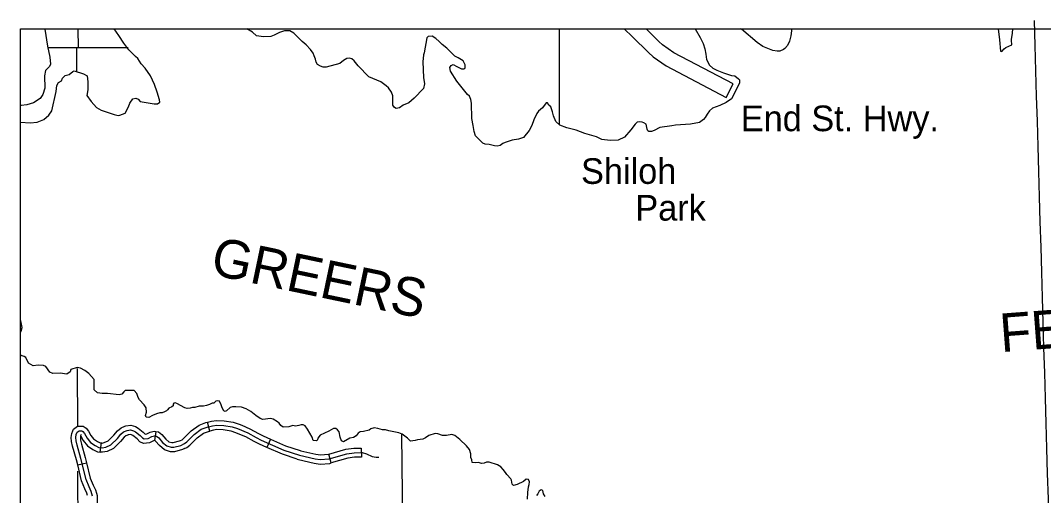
# Model space of a CAD drawing. Extents: x 1212896 to 1368412, y 378476 to 478763.
# Drawn here: x 1257400 to 1274256, y 429817 to 437641 of the extents above; entities that cross this region are included whole.
import ezdxf

# ---------------------------------------------------------------- set-up
doc = ezdxf.new("R2010")
doc.units = 0
for name, color, linetype in [('1', 7, 'Continuous'), ('Level 10', 7, 'Continuous'), ('Level 31', 7, 'Continuous'), ('Level 4', 7, 'Continuous'), ('Level 41', 7, 'Continuous'), ('Level 5', 7, 'Continuous'), ('Level 6', 7, 'Continuous'), ('Level 60', 7, 'Continuous'), ('Level 7', 7, 'Continuous'), ('Level 9', 7, 'Continuous')]:
    doc.layers.add(name, color=color, linetype=linetype)

msp = doc.modelspace()

# ---------------------------------------------------------------- linework, layer by layer
at = {"layer": '1'}
msp.add_lwpolyline([(1257400, 437504), (1319317, 437504), (1319317, 388319), (1257400, 388319)], close=True, dxfattribs=at)
at = {"layer": 'Level 10'}
msp.add_line((1269029, 436374), (1269145, 436596), dxfattribs=at)
for points in [[(1267347, 437504), (1267485, 437373), (1267745, 437111), (1267825, 437042), (1268037, 436896), (1269029, 436374)], [(1269145, 436596), (1268166, 437110), (1267978, 437240), (1267915, 437294), (1267707, 437504)]]:
    msp.add_lwpolyline(points, dxfattribs=at)
at = {"layer": 'Level 31'}
for p, q in [((1260518, 430879), (1260481, 431025)), ((1259629, 430873), (1259606, 430725)), ((1260987, 430836), (1260987, 430836)), ((1258716, 430534), (1258735, 430683)), ((1259178, 430819), (1259178, 430819)), ((1259606, 430725), (1259611, 430724)), ((1261521, 430745), (1261461, 430607)), ((1261461, 430607), (1261461, 430607)), ((1262522, 430354), (1262480, 430498)), ((1263016, 430600), (1263017, 430450)), ((1258343, 430321), (1258489, 430357))]:
    msp.add_line(p, q, dxfattribs=at)
for points in [[(1260038, 430725), (1260062, 430737), (1260091, 430760), (1260213, 430881), (1260342, 430978), (1260454, 431018), (1260481, 431025)], [(1260481, 431025), (1260550, 431042), (1260631, 431054), (1260757, 431046), (1260906, 431023), (1261002, 430993), (1261045, 430975)], [(1258343, 430321), (1258322, 430406), (1258259, 430630), (1258243, 430706), (1258237, 430774), (1258244, 430840), (1258262, 430881)], [(1258262, 430881), (1258274, 430909), (1258340, 430957), (1258431, 430962), (1258482, 430929), (1258520, 430880), (1258561, 430805), (1258606, 430749), (1258667, 430708), (1258714, 430685), (1258735, 430683)], [(1258589, 429808), (1258567, 429885), (1258531, 429958), (1258481, 430082), (1258396, 430425), (1258333, 430648), (1258319, 430718), (1258314, 430773), (1258319, 430821), (1258336, 430860), (1258366, 430882), (1258410, 430884), (1258430, 430872), (1258456, 430838), (1258497, 430763), (1258553, 430692), (1258629, 430641), (1258692, 430611), (1258749, 430604), (1258805, 430615), (1258890, 430652), (1258997, 430758), (1259055, 430828), (1259099, 430866), (1259156, 430890), (1259215, 430900), (1259263, 430885), (1259293, 430866), (1259371, 430805), (1259409, 430766), (1259439, 430752), (1259505, 430756), (1259563, 430788), (1259608, 430799), (1259641, 430794), (1259678, 430765), (1259742, 430692), (1259810, 430636), (1259883, 430612), (1259926, 430612), (1260045, 430644), (1260103, 430672), (1260142, 430703), (1260263, 430823), (1260379, 430910), (1260476, 430945), (1260565, 430967), (1260634, 430977), (1260749, 430970), (1260888, 430949), (1260975, 430921), (1261146, 430850), (1261284, 430771), (1261367, 430728), (1261741, 430566), (1262000, 430481), (1262254, 430423), (1262339, 430409), (1262487, 430420), (1262778, 430506), (1262897, 430522), (1263031, 430524), (1263104, 430505), (1263196, 430459), (1263262, 430447), (1263303, 430450)], [(1258735, 430683), (1258747, 430681), (1258782, 430688), (1258846, 430716), (1258941, 430810), (1259000, 430882), (1259059, 430932), (1259120, 430958)], [(1259120, 430958), (1259135, 430964), (1259221, 430978), (1259295, 430955), (1259337, 430928), (1259422, 430861), (1259454, 430829), (1259483, 430831), (1259535, 430860), (1259605, 430877), (1259629, 430873)], [(1259629, 430873), (1259673, 430866), (1259731, 430820), (1259795, 430747), (1259847, 430704), (1259895, 430689), (1259916, 430689), (1260018, 430716), (1260038, 430725)], [(1260104, 430591), (1260142, 430609), (1260191, 430648), (1260311, 430767), (1260414, 430845), (1260498, 430874), (1260518, 430879)], [(1260987, 430836), (1260950, 430852), (1260872, 430877), (1260741, 430897), (1260637, 430903), (1260579, 430895), (1260518, 430879)], [(1261461, 430607), (1261336, 430662), (1261249, 430706), (1261113, 430783), (1260987, 430836)], [(1261045, 430975), (1261180, 430918), (1261320, 430838), (1261400, 430798), (1261521, 430745)], [(1258400, 430822), (1258391, 430802), (1258388, 430773), (1258392, 430728), (1258405, 430666), (1258468, 430444), (1258489, 430357)], [(1258391, 430802), (1258395, 430797), (1258436, 430722), (1258503, 430638), (1258592, 430577), (1258672, 430539), (1258716, 430534)], [(1259178, 430819), (1259138, 430803), (1259108, 430777), (1259051, 430708), (1258932, 430590), (1258828, 430544), (1258752, 430529), (1258716, 430534)], [(1259611, 430724), (1259590, 430719), (1259527, 430684), (1259426, 430677), (1259365, 430704), (1259322, 430750), (1259251, 430805), (1259232, 430817), (1259210, 430824), (1259176, 430819)], [(1260104, 430591), (1260071, 430574), (1259936, 430539), (1259872, 430539), (1259773, 430571), (1259690, 430639), (1259627, 430711), (1259611, 430724), (1259606, 430725)], [(1261521, 430745), (1261768, 430637), (1262007, 430559)], [(1261960, 430417), (1261715, 430497), (1261461, 430607)], [(1262007, 430559), (1262021, 430555), (1262268, 430498), (1262342, 430486), (1262473, 430496), (1262480, 430498)], [(1262480, 430498), (1262761, 430581), (1262891, 430599), (1263016, 430600)], [(1258507, 429817), (1258495, 429857), (1258461, 429927), (1258408, 430059), (1258343, 430321)], [(1258489, 430357), (1258551, 430105), (1258598, 429988), (1258636, 429912), (1258651, 429859)], [(1261960, 430417), (1261980, 430410), (1262240, 430350), (1262336, 430335), (1262500, 430347), (1262522, 430354)], [(1263017, 430450), (1262902, 430449), (1262793, 430434), (1262522, 430354)], [(1258651, 429859), (1258663, 429819), (1258665, 429672), (1258634, 429544), (1258544, 429305)]]:
    msp.add_lwpolyline(points, dxfattribs=at)
at = {"layer": 'Level 4'}
msp.add_lwpolyline([(1259177, 437190), (1258356, 437190), (1258327, 437190), (1257855, 437189)], dxfattribs=at)
at = {"layer": 'Level 5'}
for points in [[(1258356, 437190), (1258353, 437504)], [(1258328, 436789), (1258327, 437190)], [(1257414, 432114), (1257400, 432114)], [(1258343, 430962), (1258338, 431911)], [(1263698, 429354), (1263684, 430823)], [(1258352, 429250), (1258347, 430216)]]:
    msp.add_lwpolyline(points, dxfattribs=at)
at = {"layer": 'Level 6'}
msp.add_lwpolyline([(1266273, 437504), (1266274, 437202), (1266276, 435924)], dxfattribs=at)
at = {"layer": 'Level 60'}
msp.add_spline([(1275538, 388463), (1274493, 424373), (1274106, 437641)], degree=3, dxfattribs=at)
at = {"layer": 'Level 9'}
for points in [[(1257802, 437504), (1257804, 437499), (1257845, 437219), (1257884, 437036), (1257893, 436920), (1257879, 436881), (1257815, 436817), (1257794, 436731), (1257800, 436524), (1257770, 436424), (1257725, 436355), (1257615, 436284), (1257505, 436252), (1257414, 436240), (1257400, 436237)], [(1257400, 435966), (1257561, 435953), (1257677, 435964), (1257787, 436011), (1257868, 436084), (1257915, 436152), (1257989, 436473), (1258001, 436572), (1258028, 436619), (1258076, 436646), (1258093, 436690), (1258137, 436737), (1258205, 436753), (1258265, 436801), (1258287, 436810), (1258438, 436761), (1258500, 436732), (1258512, 436628), (1258510, 436501), (1258496, 436406), (1258565, 436309), (1258652, 436209), (1258730, 436166), (1258946, 436090), (1259012, 436076), (1259040, 436080), (1259124, 436117), (1259181, 436218), (1259201, 436279), (1259251, 436349), (1259302, 436359), (1259337, 436344), (1259370, 436305), (1259604, 436266), (1259657, 436267), (1259699, 436295), (1259693, 436333), (1259654, 436461), (1259607, 436586), (1259544, 436732), (1259457, 436857), (1259389, 436925), (1259334, 437015), (1259293, 437047), (1259188, 437159), (1259104, 437265), (1259023, 437396), (1258944, 437503), (1258944, 437504)], [(1264027, 436958), (1264039, 436704), (1264059, 436595), (1264041, 436523), (1263884, 436359), (1263801, 436283), (1263708, 436247), (1263643, 436203), (1263592, 436190), (1263562, 436209), (1263536, 436246), (1263533, 436398), (1263512, 436462), (1263466, 436530), (1263426, 436566), (1263336, 436631), (1263139, 436711), (1262964, 436895), (1262899, 436978), (1262858, 437012), (1262820, 437023), (1262780, 437016), (1262721, 436983), (1262662, 436933), (1262437, 436872), (1262387, 436870), (1262342, 436886), (1262295, 436916), (1262271, 436954), (1262260, 437003), (1262241, 437059), (1262220, 437103), (1262178, 437162), (1262106, 437241), (1262039, 437295), (1261922, 437416), (1261905, 437430), (1261836, 437469), (1261748, 437472), (1261667, 437443), (1261581, 437397), (1261525, 437377), (1261406, 437373), (1261289, 437390), (1261223, 437446), (1261131, 437504)], [(1268518, 437504), (1268600, 437360), (1268646, 437262), (1268674, 437175), (1268690, 437087)], [(1269797, 437148), (1269630, 437214), (1269536, 437279), (1269281, 437498), (1269271, 437504)], [(1270102, 437504), (1270103, 437468), (1270095, 437388), (1270069, 437300), (1270038, 437227), (1269994, 437181), (1269972, 437165), (1269911, 437137), (1269868, 437134), (1269797, 437148)], [(1273511, 437504), (1273533, 437325), (1273549, 437135), (1273568, 437128), (1273606, 437172), (1273635, 437196), (1273731, 437238), (1273734, 437263), (1273727, 437293), (1273728, 437327), (1273745, 437433), (1273748, 437504)], [(1268132, 435905), (1267936, 435876), (1267841, 435829), (1267797, 435815), (1267752, 435811), (1267738, 435823), (1267728, 435850), (1267711, 435931), (1267669, 435955), (1267641, 435967), (1267606, 435973), (1267559, 435967), (1267529, 435936), (1267459, 435841), (1267350, 435719), (1267247, 435669), (1267115, 435666), (1266977, 435679), (1266892, 435726), (1266696, 435781), (1266555, 435835), (1266404, 435875), (1266285, 435916), (1266223, 435977), (1266184, 436071), (1266167, 436136), (1266136, 436218), (1266108, 436244), (1266086, 436286), (1266060, 436287), (1266003, 436203), (1265933, 436147), (1265907, 436109), (1265859, 436005), (1265823, 435909), (1265782, 435830), (1265687, 435716), (1265606, 435686), (1265501, 435669), (1265386, 435631), (1265346, 435615), (1265301, 435583), (1265256, 435572), (1265213, 435574), (1265122, 435598), (1265057, 435606), (1265018, 435621), (1264897, 435743), (1264874, 435811), (1264861, 435909), (1264837, 436028), (1264834, 436277), (1264820, 436340), (1264797, 436393), (1264767, 436422), (1264591, 436644), (1264488, 436808), (1264472, 436869), (1264498, 436901), (1264531, 436918), (1264587, 436883), (1264666, 436845), (1264704, 436845), (1264723, 436851), (1264728, 436867), (1264728, 436912), (1264695, 436976), (1264614, 437026), (1264558, 437054), (1264423, 437186), (1264349, 437243), (1264297, 437297), (1264246, 437342), (1264185, 437381), (1264120, 437376), (1264097, 437354), (1264051, 437106), (1264039, 437075), (1264027, 436958)], [(1268690, 437087), (1268703, 436998), (1268752, 436906), (1268808, 436854), (1268876, 436821), (1268982, 436780), (1269048, 436757), (1269117, 436737), (1269170, 436728), (1269229, 436682), (1269245, 436665), (1269249, 436616), (1269196, 436509)], [(1269196, 436509), (1269114, 436349), (1269028, 436288), (1268924, 436243), (1268804, 436198), (1268755, 436155), (1268714, 436099), (1268683, 436043), (1268652, 436011), (1268587, 435959), (1268440, 435935), (1268193, 435915), (1268132, 435905)], [(1257413, 432666), (1257400, 432705)], [(1257400, 432502), (1257413, 432522), (1257426, 432587), (1257413, 432666)], [(1260854, 431268), (1260797, 431212), (1260774, 431204), (1260749, 431210), (1260722, 431262), (1260709, 431311), (1260680, 431371), (1260647, 431379), (1260619, 431372), (1260584, 431341), (1260561, 431337), (1260514, 431315), (1260468, 431300), (1260416, 431291), (1260346, 431288), (1260272, 431267), (1260234, 431267), (1260194, 431256), (1260145, 431252), (1260108, 431263), (1259979, 431332), (1259950, 431343), (1259929, 431338), (1259918, 431323), (1259915, 431294), (1259892, 431278), (1259844, 431257), (1259821, 431231), (1259805, 431213), (1259771, 431198), (1259734, 431180), (1259697, 431178), (1259643, 431164), (1259575, 431134), (1259517, 431102), (1259473, 431110), (1259463, 431136), (1259477, 431193), (1259471, 431262), (1259436, 431312), (1259362, 431393), (1259341, 431432), (1259317, 431498), (1259274, 431546), (1259126, 431546), (1259102, 431527), (1259072, 431487), (1259025, 431476), (1258835, 431498), (1258747, 431500), (1258670, 431509), (1258613, 431560), (1258613, 431726), (1258527, 431828), (1258461, 431876), (1258387, 431915), (1258334, 431925), (1258228, 431895), (1258219, 431857), (1258166, 431817), (1258055, 431834), (1257934, 431825), (1257885, 431849), (1257818, 431942), (1257778, 431960), (1257690, 431967), (1257611, 431951), (1257535, 431997), (1257488, 432090), (1257462, 432106), (1257400, 432129)], [(1265354, 430248), (1265313, 430289), (1265262, 430322), (1265122, 430369), (1265079, 430366), (1265040, 430351), (1265004, 430346), (1264941, 430362), (1264889, 430355), (1264841, 430362), (1264835, 430406), (1264823, 430442), (1264821, 430502), (1264798, 430573), (1264748, 430634), (1264637, 430739), (1264554, 430804), (1264505, 430820), (1264417, 430808), (1264352, 430808), (1264279, 430831), (1264235, 430839), (1264126, 430808), (1264071, 430766), (1264032, 430743), (1263942, 430735), (1263905, 430726), (1263825, 430715), (1263777, 430760), (1263688, 430828), (1263632, 430849), (1263470, 430882), (1263417, 430899), (1263365, 430899), (1263287, 430924), (1263228, 430930), (1263175, 430915), (1263144, 430895), (1263053, 430873), (1262997, 430864), (1262965, 430843), (1262933, 430800), (1262885, 430771), (1262827, 430762), (1262722, 430700), (1262689, 430719), (1262668, 430777), (1262653, 430865), (1262623, 430900), (1262594, 430919), (1262556, 430919), (1262482, 430875), (1262336, 430810), (1262300, 430763), (1262294, 430735), (1262277, 430717), (1262220, 430723), (1262208, 430776), (1262129, 430913), (1262092, 430967), (1262057, 430982), (1262025, 430983), (1261989, 430970), (1261934, 430960), (1261885, 430972), (1261824, 430951), (1261726, 430943), (1261688, 430973), (1261665, 431009), (1261636, 431033), (1261564, 431077), (1261518, 431085), (1261396, 431071), (1261351, 431087), (1261278, 431137), (1261197, 431203), (1261120, 431244), (1261043, 431270), (1260946, 431278), (1260892, 431277), (1260854, 431268)], [(1265753, 429760), (1265759, 429869), (1265771, 429959), (1265784, 429998), (1265787, 430043), (1265770, 430083), (1265733, 430085), (1265689, 430049), (1265581, 430000), (1265522, 429983), (1265501, 430004), (1265491, 430070), (1265482, 430090), (1265412, 430163), (1265393, 430198), (1265354, 430248)], [(1266044, 429799), (1266019, 429846), (1266005, 429902), (1265977, 429910), (1265947, 429891), (1265926, 429846), (1265900, 429816)]]:
    msp.add_lwpolyline(points, dxfattribs=at)

# ---------------------------------------------------------------- texts
at = {"layer": 'Level 41'}
msp.add_text('End St. Hwy.', height=422.4, dxfattribs=at).set_placement((1269268, 435818))
at = {"layer": 'Level 7'}
for s, p in [('Shiloh', (1266636, 434950)), ('Park', (1267530, 434345))]:
    msp.add_text(s, height=422.4, dxfattribs=at).set_placement(p)
at = {"layer": 'Level 9'}
for s, rotation, p in [('GREERS', 348.162, (1260510, 433464)), ('FERRY', 4.3267, (1273557, 432178))]:
    msp.add_text(s, height=633.6, rotation=rotation, dxfattribs=at).set_placement(p)

doc.saveas('drawing.dxf')
